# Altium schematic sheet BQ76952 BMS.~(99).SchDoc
size A3; SheetNumber: 9; SheetTotal: 10
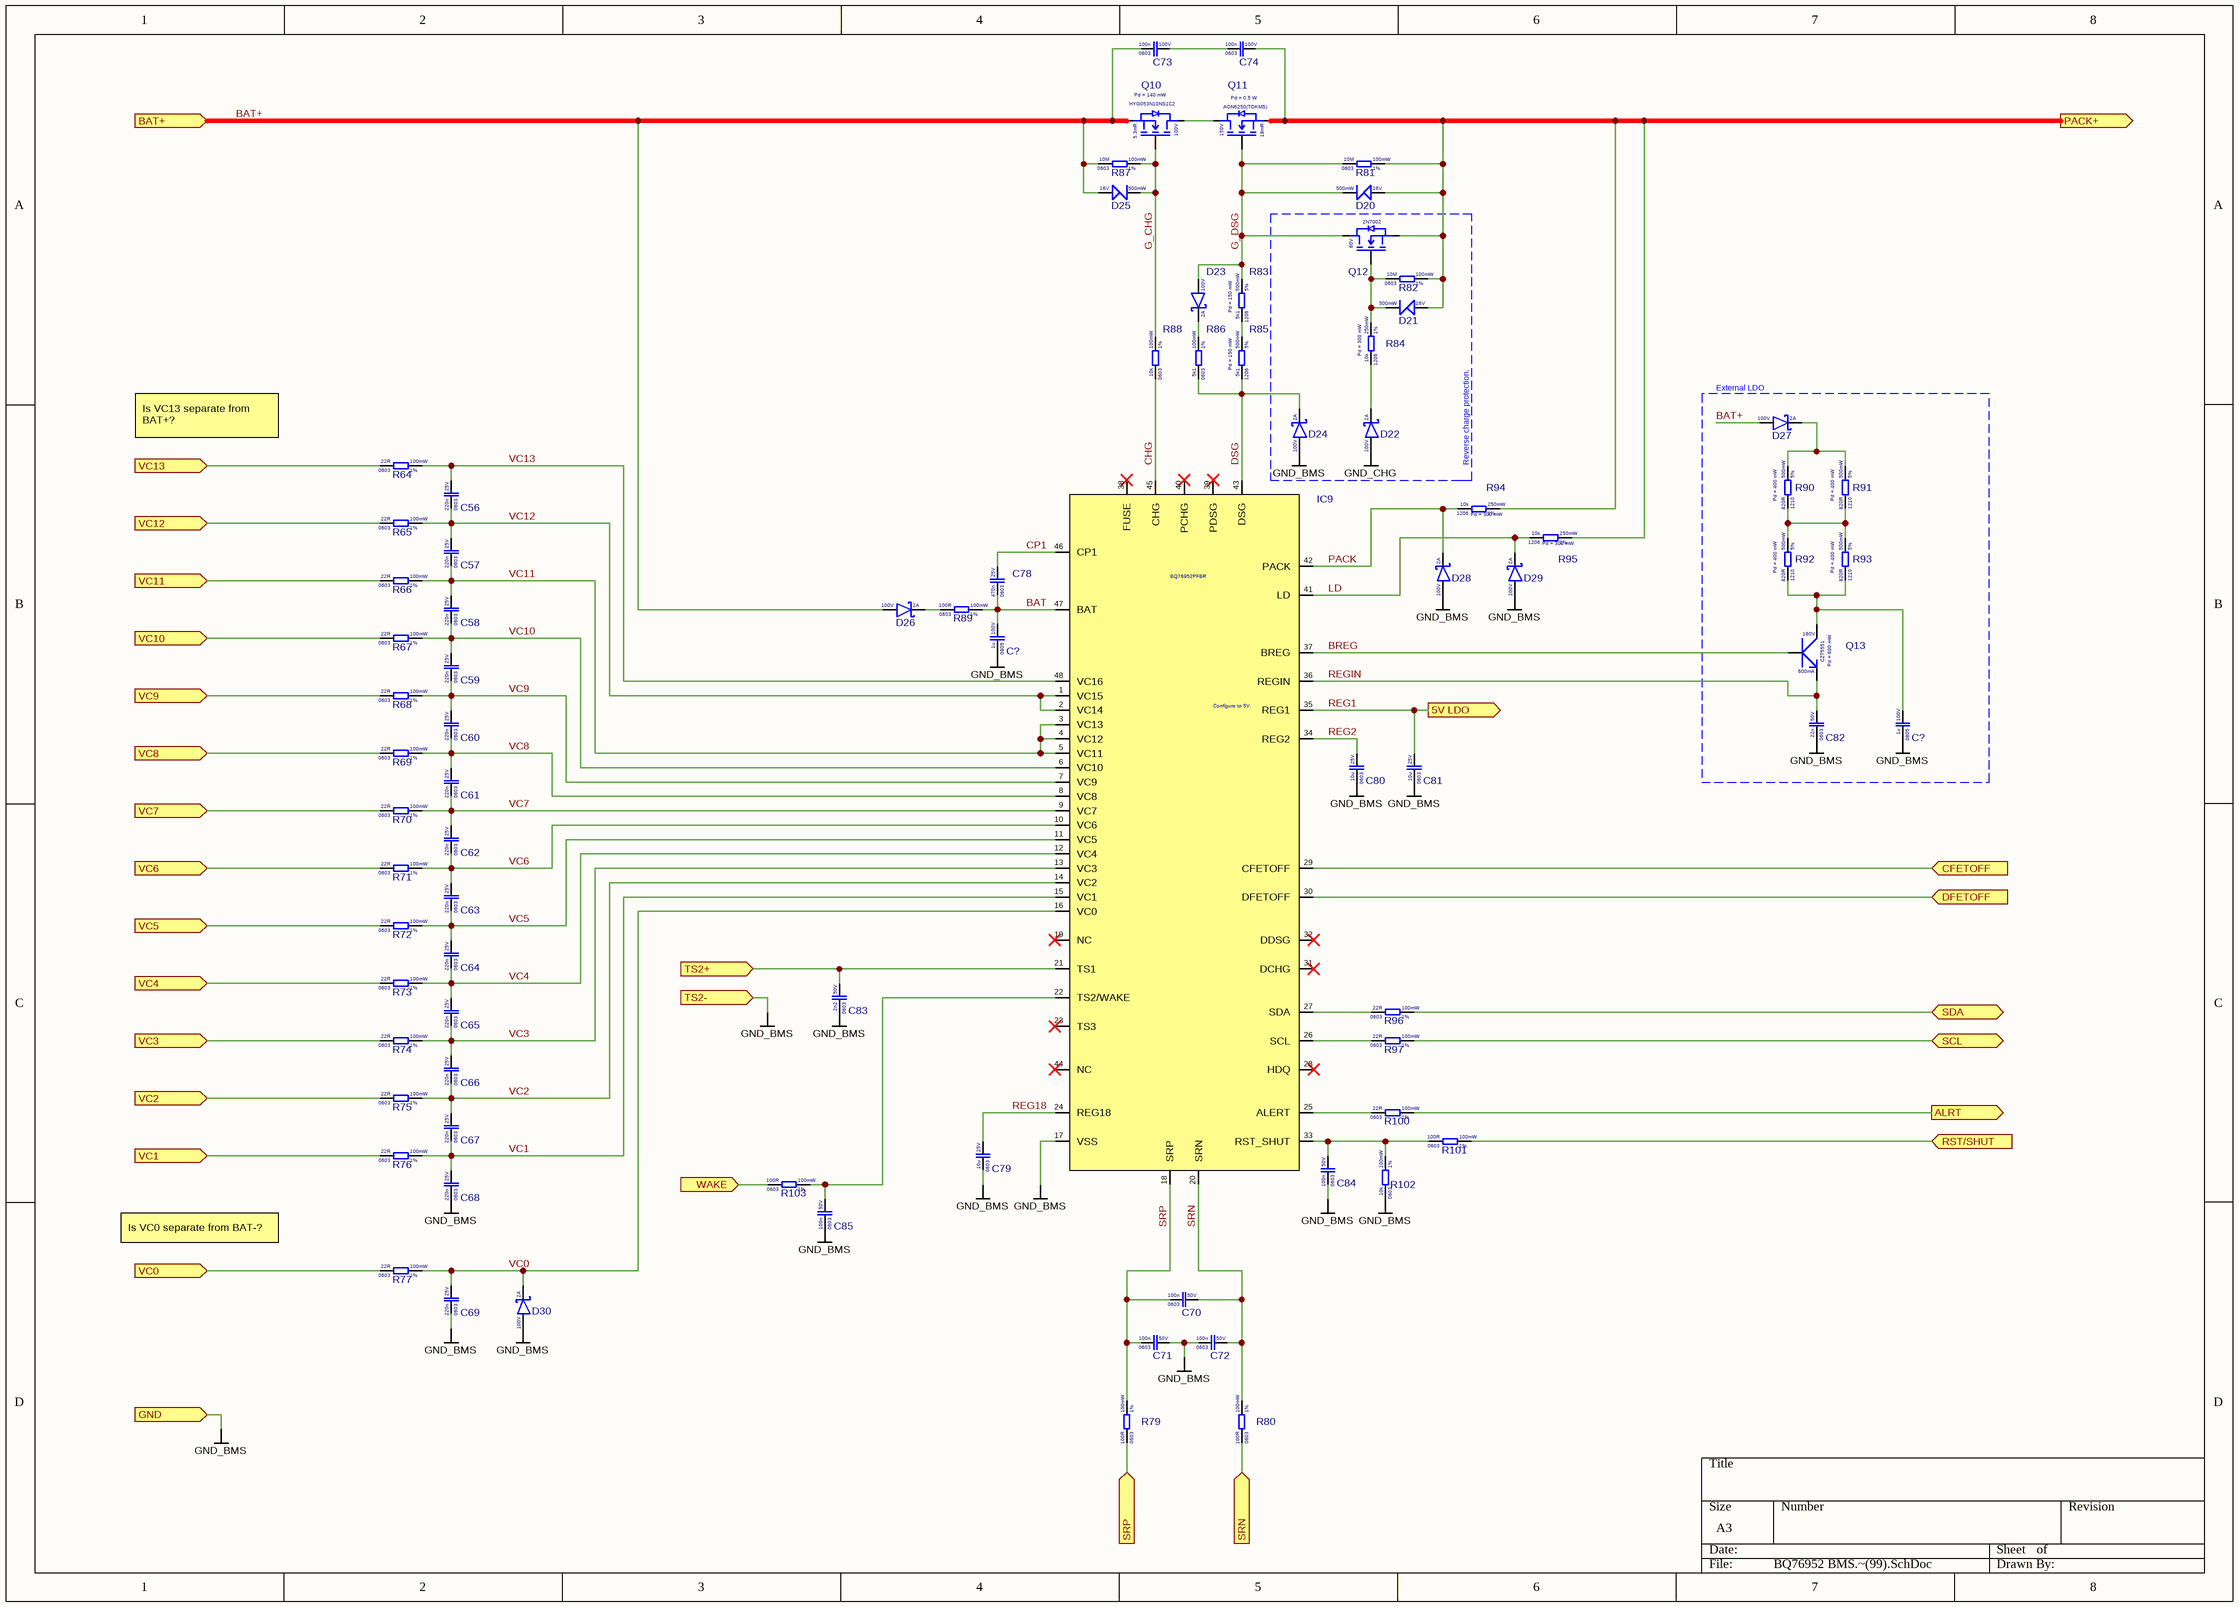
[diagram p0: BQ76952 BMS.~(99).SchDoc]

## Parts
(Parts that share a designator on the sheet are numbered #1, #2 ... from top to bottom, then left to right.)
C56  Voltage Rating: 25V  Case Code (Imperial): 0603  Capacitance: 220n  [CAP 0603]  (hidden comment: CL10B224KA8NNNC)
C57  Voltage Rating: 25V  Case Code (Imperial): 0603  Capacitance: 220n  [CAP 0603]  (hidden comment: CL10B224KA8NNNC)
C58  Voltage Rating: 25V  Case Code (Imperial): 0603  Capacitance: 220n  [CAP 0603]  (hidden comment: CL10B224KA8NNNC)
C59  Voltage Rating: 25V  Case Code (Imperial): 0603  Capacitance: 220n  [CAP 0603]  (hidden comment: CL10B224KA8NNNC)
C60  Voltage Rating: 25V  Case Code (Imperial): 0603  Capacitance: 220n  [CAP 0603]  (hidden comment: CL10B224KA8NNNC)
C61  Voltage Rating: 25V  Case Code (Imperial): 0603  Capacitance: 220n  [CAP 0603]  (hidden comment: CL10B224KA8NNNC)
C62  Voltage Rating: 25V  Case Code (Imperial): 0603  Capacitance: 220n  [CAP 0603]  (hidden comment: CL10B224KA8NNNC)
C63  Voltage Rating: 25V  Case Code (Imperial): 0603  Capacitance: 220n  [CAP 0603]  (hidden comment: CL10B224KA8NNNC)
C64  Voltage Rating: 25V  Case Code (Imperial): 0603  Capacitance: 220n  [CAP 0603]  (hidden comment: CL10B224KA8NNNC)
C65  Voltage Rating: 25V  Case Code (Imperial): 0603  Capacitance: 220n  [CAP 0603]  (hidden comment: CL10B224KA8NNNC)
C66  Voltage Rating: 25V  Case Code (Imperial): 0603  Capacitance: 220n  [CAP 0603]  (hidden comment: CL10B224KA8NNNC)
C67  Voltage Rating: 25V  Case Code (Imperial): 0603  Capacitance: 220n  [CAP 0603]  (hidden comment: CL10B224KA8NNNC)
C68  Voltage Rating: 25V  Case Code (Imperial): 0603  Capacitance: 220n  [CAP 0603]  (hidden comment: CL10B224KA8NNNC)
C69  Voltage Rating: 25V  Case Code (Imperial): 0603  Capacitance: 220n  [CAP 0603]  (hidden comment: CL10B224KA8NNNC)
C70  Voltage Rating: 50V  Case Code (Imperial): 0603  Capacitance: 100n  [CAP 0603]  (hidden comment: CC0603KRX7R9BB104)
C71  Voltage Rating: 50V  Case Code (Imperial): 0603  Capacitance: 100n  [CAP 0603]  (hidden comment: CC0603KRX7R9BB104)
C72  Voltage Rating: 50V  Case Code (Imperial): 0603  Capacitance: 100n  [CAP 0603]  (hidden comment: CC0603KRX7R9BB104)
C73  Voltage Rating: 100V  Case Code (Imperial): 0603  Capacitance: 100n  [CAP 0603]  (hidden comment: CC0603KRX7R0BB104)
C74  Voltage Rating: 100V  Case Code (Imperial): 0603  Capacitance: 100n  [CAP 0603]  (hidden comment: CC0603KRX7R0BB104)
C78  Voltage Rating: 25V  Case Code (Imperial): 0603  Capacitance: 470n  [CAP 0603]  (hidden comment: CL10B474KA8NNNC)
C79  Voltage Rating: 25V  Case Code (Imperial): 0603  Capacitance: 10u  [CAP 0603]  (hidden comment: CL10A106MA8NRNC)
C80  Voltage Rating: 25V  Case Code (Imperial): 0603  Capacitance: 10u  [CAP 0603]  (hidden comment: CL10A106MA8NRNC)
C81  Voltage Rating: 25V  Case Code (Imperial): 0603  Capacitance: 10u  [CAP 0603]  (hidden comment: CL10A106MA8NRNC)
C82  Voltage Rating: 50V  Case Code (Imperial): 0603  Capacitance: 22n  [CAP 0603]  (hidden comment: CL10B223KB8NNNC)
C83  Voltage Rating: 50V  Case Code (Imperial): 0603  Capacitance: 2n2  [CAP 0603]  (hidden comment: 0603B222K500NT)
C84  Voltage Rating: 50V  Case Code (Imperial): 0603  Capacitance: 100n  [CAP 0603]  (hidden comment: CC0603KRX7R9BB104)
C85  Voltage Rating: 50V  Case Code (Imperial): 0603  Capacitance: 100n  [CAP 0603]  (hidden comment: CC0603KRX7R9BB104)
C?#1  Voltage Rating: 100V  Case Code (Imperial): 0805  Capacitance: 1u  [Cap_0805]  (hidden comment: CC0805KKX7R0BB105)
C?#2  Voltage Rating: 100V  Case Code (Imperial): 0805  Capacitance: 1u  [Cap_0805]  (hidden comment: CC0805KKX7R0BB105)
D20  Power Rating: 500mW  Reverse Voltage: 16V  [SOD-123]  (hidden comment: BZT52C16)
D21  Power Rating: 500mW  Reverse Voltage: 16V  [SOD-123]  (hidden comment: BZT52C16)
D22  Forward Current: 2A  Reverse Voltage: 100V  [SMAF]  (hidden comment: SS210F)
D23  Forward Current: 2A  Reverse Voltage: 100V  [SMAF]  (hidden comment: SS210F)
D24  Forward Current: 2A  Reverse Voltage: 100V  [SMAF]  (hidden comment: SS210F)
D25  Power Rating: 500mW  Reverse Voltage: 16V  [SOD-123]  (hidden comment: BZT52C16)
D26  Forward Current: 2A  Reverse Voltage: 100V  [SMAF]  (hidden comment: SS210F)
D27  Forward Current: 2A  Reverse Voltage: 100V  [SMAF]  (hidden comment: SS210F)
D28  Forward Current: 2A  Reverse Voltage: 100V  [SMAF]  (hidden comment: SS210F)
D29  Forward Current: 2A  Reverse Voltage: 100V  [SMAF]  (hidden comment: SS210F)
D30  Forward Current: 2A  Reverse Voltage: 100V  [SMAF]  (hidden comment: SS210F)
IC9  BQ76952PFBR  [TQFP-48 PFB]
Q10  Pd = 140 mW  Rds: 5.3mR  Voltage: 100V  [PDFN5*6-8L]
Q11  Pd = 0.5 W  Rds: 18mR  Voltage: 150V  [DFN-8 (5x6)]
Q12  Voltage: 60V  [SOT-23 GSD]  (hidden comment: 2N7002)
Q13  Pd = 600 mW  Current: 600mA  Voltage: 160V  [SOT-223 NPN]
R64  Resistance Tolerance: 1%  Resistance: 22R  Power Rating: 100mW  Case Code (Imperial): 0603  [RES_0603]  (hidden comment: 0603WAF220JT5E)
R65  Resistance Tolerance: 1%  Resistance: 22R  Power Rating: 100mW  Case Code (Imperial): 0603  [RES_0603]  (hidden comment: 0603WAF220JT5E)
R66  Resistance Tolerance: 1%  Resistance: 22R  Power Rating: 100mW  Case Code (Imperial): 0603  [RES_0603]  (hidden comment: 0603WAF220JT5E)
R67  Resistance Tolerance: 1%  Resistance: 22R  Power Rating: 100mW  Case Code (Imperial): 0603  [RES_0603]  (hidden comment: 0603WAF220JT5E)
R68  Resistance Tolerance: 1%  Resistance: 22R  Power Rating: 100mW  Case Code (Imperial): 0603  [RES_0603]  (hidden comment: 0603WAF220JT5E)
R69  Resistance Tolerance: 1%  Resistance: 22R  Power Rating: 100mW  Case Code (Imperial): 0603  [RES_0603]  (hidden comment: 0603WAF220JT5E)
R70  Resistance Tolerance: 1%  Resistance: 22R  Power Rating: 100mW  Case Code (Imperial): 0603  [RES_0603]  (hidden comment: 0603WAF220JT5E)
R71  Resistance Tolerance: 1%  Resistance: 22R  Power Rating: 100mW  Case Code (Imperial): 0603  [RES_0603]  (hidden comment: 0603WAF220JT5E)
R72  Resistance Tolerance: 1%  Resistance: 22R  Power Rating: 100mW  Case Code (Imperial): 0603  [RES_0603]  (hidden comment: 0603WAF220JT5E)
R73  Resistance Tolerance: 1%  Resistance: 22R  Power Rating: 100mW  Case Code (Imperial): 0603  [RES_0603]  (hidden comment: 0603WAF220JT5E)
R74  Resistance Tolerance: 1%  Resistance: 22R  Power Rating: 100mW  Case Code (Imperial): 0603  [RES_0603]  (hidden comment: 0603WAF220JT5E)
R75  Resistance Tolerance: 1%  Resistance: 22R  Power Rating: 100mW  Case Code (Imperial): 0603  [RES_0603]  (hidden comment: 0603WAF220JT5E)
R76  Resistance Tolerance: 1%  Resistance: 22R  Power Rating: 100mW  Case Code (Imperial): 0603  [RES_0603]  (hidden comment: 0603WAF220JT5E)
R77  Resistance Tolerance: 1%  Resistance: 22R  Power Rating: 100mW  Case Code (Imperial): 0603  [RES_0603]  (hidden comment: 0603WAF220JT5E)
R79  Resistance Tolerance: 1%  Resistance: 100R  Power Rating: 100mW  Case Code (Imperial): 0603  [RES_0603]  (hidden comment: 0603WAF1000T5E)
R80  Resistance Tolerance: 1%  Resistance: 100R  Power Rating: 100mW  Case Code (Imperial): 0603  [RES_0603]  (hidden comment: 0603WAF1000T5E)
R81  Resistance Tolerance: 1%  Resistance: 10M  Power Rating: 100mW  Case Code (Imperial): 0603  [RES_0603]  (hidden comment: 0603WAF1005T5E)
R82  Resistance Tolerance: 1%  Resistance: 10M  Power Rating: 100mW  Case Code (Imperial): 0603  [RES_0603]  (hidden comment: 0603WAF1005T5E)
R83  Pd = 150 mW  Resistance Tolerance: 5%  Resistance: 5k1  Power Rating: 500mW  Case Code (Imperial): 1206  [RES_1206]
R84  Pd = 300 mW  Resistance Tolerance: 1%  Resistance: 10k  Power Rating: 250mW  Case Code (Imperial): 1206  [RES_1206]
R85  Pd = 150 mW  Resistance Tolerance: 5%  Resistance: 5k1  Power Rating: 500mW  Case Code (Imperial): 1206  [RES_1206]
R86  Resistance Tolerance: 1%  Resistance: 5k1  Power Rating: 100mW  Case Code (Imperial): 0603  [RES_0603]  (hidden comment: 0603WAF5101T5E)
R87  Resistance Tolerance: 1%  Resistance: 10M  Power Rating: 100mW  Case Code (Imperial): 0603  [RES_0603]  (hidden comment: 0603WAF1005T5E)
R88  Resistance Tolerance: 1%  Resistance: 10k  Power Rating: 100mW  Case Code (Imperial): 0603  [RES_0603]  (hidden comment: 0603WAF1002T5E)
R89  Resistance Tolerance: 1%  Resistance: 100R  Power Rating: 100mW  Case Code (Imperial): 0603  [RES_0603]  (hidden comment: 0603WAF1000T5E)
R90  Pd = 400 mW  Resistance Tolerance: 5%  Resistance: 820R  Power Rating: 500mW  Case Code (Imperial): 1210  [RES_1210]
R91  Pd = 400 mW  Resistance Tolerance: 5%  Resistance: 820R  Power Rating: 500mW  Case Code (Imperial): 1210  [RES_1210]
R92  Pd = 400 mW  Resistance Tolerance: 5%  Resistance: 820R  Power Rating: 500mW  Case Code (Imperial): 1210  [RES_1210]
R93  Pd = 400 mW  Resistance Tolerance: 5%  Resistance: 820R  Power Rating: 500mW  Case Code (Imperial): 1210  [RES_1210]
R94  Pd = 300 mW  Resistance Tolerance: 1%  Resistance: 10k  Power Rating: 250mW  Case Code (Imperial): 1206  [RES_1206]
R95  Pd = 300 mW  Resistance Tolerance: 1%  Resistance: 10k  Power Rating: 250mW  Case Code (Imperial): 1206  [RES_1206]
R96  Resistance Tolerance: 1%  Resistance: 22R  Power Rating: 100mW  Case Code (Imperial): 0603  [RES_0603]  (hidden comment: 0603WAF220JT5E)
R97  Resistance Tolerance: 1%  Resistance: 22R  Power Rating: 100mW  Case Code (Imperial): 0603  [RES_0603]  (hidden comment: 0603WAF220JT5E)
R100  Resistance Tolerance: 1%  Resistance: 22R  Power Rating: 100mW  Case Code (Imperial): 0603  [RES_0603]  (hidden comment: 0603WAF220JT5E)
R101  Resistance Tolerance: 1%  Resistance: 100R  Power Rating: 100mW  Case Code (Imperial): 0603  [RES_0603]  (hidden comment: 0603WAF1000T5E)
R102  Resistance Tolerance: 1%  Resistance: 10k  Power Rating: 100mW  Case Code (Imperial): 0603  [RES_0603]  (hidden comment: 0603WAF1002T5E)
R103  Resistance Tolerance: 1%  Resistance: 100R  Power Rating: 100mW  Case Code (Imperial): 0603  [RES_0603]  (hidden comment: 0603WAF1000T5E)

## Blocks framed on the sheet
External LDO: C82 C?#2 D27 Q13 R90-R93

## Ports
5V LDO (out, see BMS[3A]), ALRT (out, see BMS[3B], MCU[1B]), BAT+ (in, see BMS[2A], BMS[1A]), CFETOFF (in, see BMS[3B], MCU[1C]), DFETOFF (in, see BMS[3B], MCU[1C]), GND (in, see BMS[2C], MCU[1C]), PACK+ (out, see BMS[3A], BMS[8A], Charger BQ25756[1A], CHARGER[1B], Power distribution[3A]), RST/SHUT (in, see BMS[3B], MCU[1C]), SCL (bidir, see BMS[3C], BMS[8C], MCU[1B]), SDA (bidir, see BMS[3C], BMS[8C], MCU[1B]), SRN (in, see BMS[3C]), SRP (in, see BMS[2C]), TS2+ (in, see BMS[2C], BMS[1C]), TS2- (in, see BMS[2C], BMS[1C]), VC0 (in, see BMS[2C], BMS[1C]), VC1 (in, see BMS[2B], BMS[1B]), VC2 (in, see BMS[2B], BMS[1B]), VC3 (in, see BMS[2B], BMS[1B]), VC4 (in, see BMS[2B], BMS[1B]), VC5 (in, see BMS[2B], BMS[1B]), VC6 (in, see BMS[2B], BMS[1B]), VC7 (in, see BMS[2B], BMS[1B]), VC8 (in, see BMS[2B], BMS[1B]), VC9 (in, see BMS[2B], BMS[1B]), VC10 (in, see BMS[2B], BMS[1B]), VC11 (in, see BMS[2B], BMS[1B]), VC12 (in, see BMS[2B], BMS[1B]), VC13 (in, see BMS[2B], BMS[1B]), WAKE (in, see BMS[3C])

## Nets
GND_BMS: C68.1 C69.1 C71.2 C72.1 C79.1 C80.1 C81.1 C82.1 C83.1 C84.1 C85.1 C?#1.1 C?#2.1 D24.A D28.A D29.A D30.A IC9.17(VSS) R102.1 ; port TS2-, port GND
GND_CHG: D22.A
ALRT: R100.2 ; port ALRT
BAT: C78.1 C?#1.2 IC9.47(BAT) R89.2
BAT+: C73.1 D25.A D26.A D27.A Q10.S R87.1 ; port BAT+
BREG: IC9.37(BREG) Q13.B
CFETOFF: IC9.29(CFETOFF) ; port CFETOFF
CHG: IC9.45(CHG) R88.1
CP1: C78.2 IC9.46(CP1)
DFETOFF: IC9.30(DFETOFF) ; port DFETOFF
DSG: D24.K IC9.43(DSG) R85.1 R86.1
G_CHG: D25.K Q10.G R87.2 R88.2
G_DSG: D20.K D23.A Q11.G Q12.D R81.1 R83.2
LD: D29.K IC9.41(LD) R95.1
PACK: D28.K IC9.42(PACK) R94.1
PACK+: C74.2 D20.A D21.A Q11.S Q12.S R81.2 R82.2 R94.2 R95.2 ; port PACK+
REG1: C81.2 IC9.35(REG1) ; port 5V LDO
REG2: C80.2 IC9.34(REG2)
REG18: C79.2 IC9.24(REG18)
REGIN: C82.2 IC9.36(REGIN) Q13.E
RST/SHUT: R101.2 ; port RST/SHUT
SCL: R97.2 ; port SCL
SDA: R96.2 ; port SDA
SRN: C70.2 C72.2 IC9.20(SRN) R80.2
SRN: R80.1 ; port SRN  [a separate net that carries the same name]
SRP: C70.1 C71.1 IC9.18(SRP) R79.2
SRP: R79.1 ; port SRP  [a separate net that carries the same name]
TS2+: C83.2 IC9.21(TS1) ; port TS2+
VC0: R77.1 ; port VC0
VC0: C69.2 D30.K IC9.16(VC0) R77.2  [a separate net that carries the same name]
VC1: R76.1 ; port VC1
VC1: C67.1 C68.2 IC9.15(VC1) R76.2  [a separate net that carries the same name]
VC2: R75.1 ; port VC2
VC2: C66.1 C67.2 IC9.14(VC2) R75.2  [a separate net that carries the same name]
VC3: R74.1 ; port VC3
VC3: C65.1 C66.2 IC9.13(VC3) R74.2  [a separate net that carries the same name]
VC4: R73.1 ; port VC4
VC4: C64.1 C65.2 IC9.12(VC4) R73.2  [a separate net that carries the same name]
VC5: R72.1 ; port VC5
VC5: C63.1 C64.2 IC9.11(VC5) R72.2  [a separate net that carries the same name]
VC6: R71.1 ; port VC6
VC6: C62.1 C63.2 IC9.10(VC6) R71.2  [a separate net that carries the same name]
VC7: R70.1 ; port VC7
VC7: C61.1 C62.2 IC9.9(VC7) R70.2  [a separate net that carries the same name]
VC8: R69.1 ; port VC8
VC8: C60.1 C61.2 IC9.8(VC8) R69.2  [a separate net that carries the same name]
VC9: R68.1 ; port VC9
VC9: C59.1 C60.2 IC9.7(VC9) R68.2  [a separate net that carries the same name]
VC10: R67.1 ; port VC10
VC10: C58.1 C59.2 IC9.6(VC10) R67.2  [a separate net that carries the same name]
VC11: R66.1 ; port VC11
VC11: C57.1 C58.2 IC9.3(VC13) IC9.4(VC12) IC9.5(VC11) R66.2  [a separate net that carries the same name]
VC12: R65.1 ; port VC12
VC12: C56.1 C57.2 IC9.1(VC15) IC9.2(VC14) R65.2  [a separate net that carries the same name]
VC13: R64.1 ; port VC13
VC13: C56.2 IC9.48(VC16) R64.2  [a separate net that carries the same name]
WAKE: R103.1 ; port WAKE
NetC73_2: C73.2 C74.1
NetC84_2: C84.2 IC9.33(RST_SHUT) R101.1 R102.2
NetC85_2: C85.2 IC9.22(TS2/WAKE) R103.2
NetC?#2_2: C?#2.2 Q13.C R92.1 R93.1
NetD21_K: D21.K Q12.G R82.1 R84.2
NetD22_K: D22.K R84.1
NetD23_K: D23.K R86.2
NetD26_K: D26.K R89.1
NetD27_K: D27.K R90.2 R91.2
NetIC9_25: IC9.25(ALERT) R100.1
NetIC9_26: IC9.26(SCL) R97.1
NetIC9_27: IC9.27(SDA) R96.1
NetQ10_D: Q10.D Q11.D
NetR83_1: R83.1 R85.2
NetR90_1: R90.1 R91.1 R92.2 R93.2

Not connected (* = marked no-connect by the designer): IC9 19(NC)* 23(TS3)* 28(HDQ)* 31(DCHG)* 32(DDSG)* 38(FUSE)* 39(PDSG)* 40(PCHG)* 44(NC)*

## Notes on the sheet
- Is VC13 separate from BAT+?
- (near R94) Reverse charge protection.
- (near IC9) Configure to 5V.
- Is VC0 separate from BAT-?

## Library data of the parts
C56-C69 = CL10B224KA8NNNC: Cap 220nF 25V 0603 X7R; Manufacturer: Samsung
C70-C72 C84 C85 = CC0603KRX7R9BB104: Cap 100nF 50V 0603 X7R; Manufacturer: Yageo
C73 C74 = CC0603KRX7R0BB104: Cap 100nF 100V 0603 X7R; Manufacturer: YAGEO
C78 = CL10B474KA8NNNC: Cap 470nF 25V 0603 X7R; Manufacturer: Samsung
C79-C81 = CL10A106MA8NRNC: Cap 10uF 25V 0603 X5R; Manufacturer: Samsung
C82 = CL10B223KB8NNNC: Cap 22nF 50V 0603 X7R; Manufacturer: Samsung
C83 = 0603B222K500NT: Cap 2n2F 50V 0603 X7R; Manufacturer: FH
C?#1 C?#2 = CC0805KKX7R0BB105: Cap 1uF 100V 0805 X7R; Manufacturer: Yageo
D20 D21 D25 = BZT52C16: Zener 16V 500mW SOD-123; Manufacturer: TWGMC
D22-D24 D26-D30 = SS210F: Schottky 100V 2A 850mVf SMAF; Manufacturer: GOODWORK
IC9 = BQ76952PFBR: BMS IC 3~16s; Manufacturer: Texas Instruments
Q10 = HYG053N10NS1C2: Nmos 100V 95A 5.3mR PDFN5x6-8L; Manufacturer: HUAYI
Q11 = AON6250(TOKMS): Nmos 150V 50A 18mR DFN-8; Manufacturer: Tokmas
Q12 = 2N7002: nMOS 60V 115mA SOT-23; Manufacturer: Jiangsu Changjing Electronics Technology Co., Ltd.
Q13 = CZT5551: NPN 160V 600mA SOT-223 1W; Manufacturer: Jiangsu
R64-R77 R96 R97 R100 = 0603WAF220JT5E: Res 22R 0603 1% 100mW 75V; Manufacturer: Uni-Royal
R79 R80 R89 R101 R103 = 0603WAF1000T5E: Res 100R 0603 1% 100mW 75V; Manufacturer: Uni-Royal
R81 R82 R87 = 0603WAF1005T5E: Res 10M 0603 1% 100mW 75V; Manufacturer: Uni-Royal
R83 R85 = HP06W2J0512T5E: Res 5k1 1206 5% 500mW 200V; Manufacturer: Uni-Royal
R84 R94 R95 = 1206W4F1002T5E: Res 10k 1206 1% 250mW 200V; Manufacturer: Uni-Royal
R86 = 0603WAF5101T5E: Res 5k1 0603 1% 100mW 75V; Manufacturer: Uni-Royal
R88 R102 = 0603WAF1002T5E: Res 10k 0603 1% 100mW 75V; Manufacturer: Uni-Royal
R90-R93 = FRC1210J821 TS: Res 820R 1210 5% 500mW 200V; Manufacturer: FOJAN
